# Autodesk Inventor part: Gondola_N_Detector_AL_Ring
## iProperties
Shininess: 64.0
Length Units: 11272
Angle Units: 11279
Time Units: 11290
Mass Units: 11286
Length Display Precision: 3
Angle Display Precision: 2
Compacted: True
Part Number: Gondola_N_Detector_AL_Ring
Document SubType Name: Modeling
Created: 2004-12
Designer: John Blackburn
Material: Aluminum-6061
Manufacturer: Standard
Standards Organization: Custom
Density: 0.0
Volumn: 0.0
Area: 0.0
PropertySet Name: Model Information
Control State: 0
Master: False
Checked Out: False
Author: John Blackburn
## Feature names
1. Extrusion1
